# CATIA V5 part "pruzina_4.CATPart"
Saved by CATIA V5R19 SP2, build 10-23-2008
Part number: Pruzina delka 19mm
Bounding box of the stored display mesh (mm): x -8 to 8, y -8 to 8, z 0 to 19
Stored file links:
  D:\DURATEC\pruzina_4.CATPart
  D:\DURATEC\pruzina_1.CATPart
  D:\DURATEC\Pohyb pruziny.CATProduct
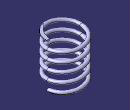
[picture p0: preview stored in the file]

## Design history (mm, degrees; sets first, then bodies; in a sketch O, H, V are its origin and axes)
External parameters (linked from other documents)
  `External.Delka pruziny` = 19 mm
  `External.Pocet zavitu` = 5
  `External.Vnitrni prumer pruziny` = 13 mm
  `External.Prumer dratu` = 1.5 mm
Set1
  Plane1: type Normal, Curve {line type PtDir, Direction (0, 0, 1), Start 0, End 19 {= `External.Delka pruziny`}, RefPoint {point type Coord, X 0, Y 0, Z 0}}, RefPoint vertex of Plane1
  Sketch1 on zx-plane, origin (0, 0, 0), H (-1, 0, 0), V (0, 0, 1)
    line L1 (6.5, 18) -> (6.5, 13)
    construction line L2 (6.5, 13) -> (-6.5, 13)
    line L3 (-6.5, 13) -> (-6.5, 18)
    construction line L4 (-6.5, 18) -> (6.5, 18)
    reference intersected line E1 through (0, 19) direction (-1, 0) from Plane1
    distance L3 L1 = 13 {= `External.Vnitrni prumer pruziny`}
    length L1 = 5
    distance L4 E1 = 1
    vertical: L1 V, L3 V
    horizontal: L2 H, L4 H
    equidistance: L1 L3 O
  Line1: type PtDir, Direction (0, 0, 1), Start 0, End 19 {= `External.Delka pruziny`}, RefPoint {point type Coord, X 0, Y 0, Z 0}
Body1 "Pruzina" (main body)
  Helix1: Pitch 3.8 {= `External.Delka pruziny` /`External.Pocet zavitu`}, TaperAngle 0, Height 19 {= Plane1.End}, Direction {line type PtDir, Direction (0, 0, 1), Start 0, End 19 {= `External.Delka pruziny`}, RefPoint {point type Coord, X 0, Y 0, Z 0}}, RefPoint {point type Coord, X 7.25 {= `External.Vnitrni prumer pruziny` /2+`External.Prumer dratu` /2}, Y 0, Z 0}
  Sketch2 on zx-plane, origin (0, 0, 0), H (-1, 0, 0), V (0, 0, 1)
    circle A1 centre (-7.25, 0) radius 0.75
    point P1 (-7.25, 0)
    reference projected point E1 (-7.25, 0) from vertex of Helix1
    radius A1 = 0.75 {= `External.Prumer dratu` /2}
    distance V A1 = 6.5 (reference)
    distance V A1 = 8 (reference)
    coincidence: P1 E1
  Rib1: profile Sketch2, centre curve Helix1
  Split1: SplitPlane xy-plane
  Split2: SplitPlane Plane1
